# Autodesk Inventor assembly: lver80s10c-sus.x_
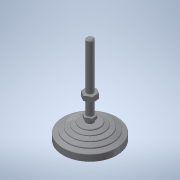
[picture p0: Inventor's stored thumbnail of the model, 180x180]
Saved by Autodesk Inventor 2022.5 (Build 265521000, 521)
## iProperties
Part Number: lver80s10c-sus.x_
Material: 一般
Document SubType Name: Assembly
Designer: ImaoCorp
Sending System: SOLIDWORKS 2017-2017317
MC: AMD64
MC_MODEL: Intel64 Family 6 Model 60 Stepping 3, GenuineIntel
OS: Windows_NT
FRU: Parasolid Version 29.0, build 201,  4-17-2017
FORMAT: text
GUISE: transmit
KEY: lver80s10c-sus
FILE: lver80s10c-sus.x_t
DATE: Mon Jul 01 18:28:16 2019
Author: ImaoCorp
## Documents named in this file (3)
- X:\14_SW2022-Inv2022\00_全2023-1023新製品(TCC)まで\l\lver80s10c-sus\LVER80S10C-SUS.iam
- X:\14_SW2022-Inv2022\00_全2023-1023新製品(TCC)まで\l\lver80s10c-sus\lver80s10c-sus_01.ipt
- X:\14_SW2022-Inv2022\00_全2023-1023新製品(TCC)まで\l\lver80s10c-sus\lver80s10c-sus_02.ipt
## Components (2 placed, 2 different names)
1. lver80s10c-sus_01
2. lver80s10c-sus_02
